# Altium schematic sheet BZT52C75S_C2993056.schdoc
size 127 x 101 mm
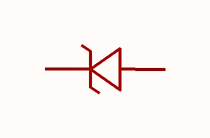
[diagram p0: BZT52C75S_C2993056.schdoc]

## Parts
D?  bzt52c75s_c2993056  [SOD-323_L1.6-W1.3-LS2.7-RD]  (value not drawn)

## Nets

Not connected (* = marked no-connect by the designer): D? 1(C) 2(A)

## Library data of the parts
D? = bzt52c75s_c2993056: 二极管配置:1个独立式;稳压值(标称值):75V;稳压值(范围):70V~79V;耗散功率(Pd):300mW;; Manufacturer: MDD(辰达半导体); AddInBom: yes; ModelId: 39bca86493a8419684ee2090e9340edf; ModelTransform: 104.3305,51.181,0,0,0,0,0,0,0; Diode Configuration: 1个独立式; Zener Voltage(Nom): 75V; Reverse Leakage Current (Ir): 100nA@56V; Pd - Power Dissipation: 300mW; Impedance(Zzt): 265Ω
